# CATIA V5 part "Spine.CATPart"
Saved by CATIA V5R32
Part number: Part1
Bounding box of the stored display mesh (mm): x 97.05 to 179.832, y -8.213 to 8.213, z -51.727 to 9.115
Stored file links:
  D:\PROJECTS\Project 2022\CATIA V5 6R 2022\Resources\Part Files\c17_catia_v6_6r2022_prt\Spine.CATPart
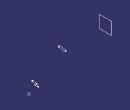
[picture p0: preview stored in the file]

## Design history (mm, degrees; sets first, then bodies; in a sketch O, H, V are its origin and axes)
Body1 (main body)
  Plane1: type Offset, RefPlane yz-plane, Offset 100
  Sketch1 on Plane1, origin (100, 0, 0), H (0, 1, 0), V (0, 0, 1)
    line L1 (-11.8744, 0) -> (18.2844, 0)
    point P1 (-11.8744, 0)
    coincidence: P1 H
    horizontal: L1 H
  Plane2: type Angle, RefPlane Plane1, Direction Sketch1, Angle 30
  Plane3: type Offset, RefPlane Plane2, Offset 75
  Plane4: type Offset, RefPlane Plane3, Offset 20
  Sketch2 on Plane4, origin (157.2724, 0, -90.8013), H (0, 1, 0), V (0.5, 0, 0.866)
    point P1 (0, 45.1194)
    coincidence: P1 V
  Sketch3 on Plane3, origin (139.9519, 0, -80.8013), H (0, 1, 0), V (0.5, 0, 0.866)
    arc A1 centre (0, 54.9362) radius 5.3671 from (5.2994, 54.0869) to (-5.2994, 54.0869) ccw
    point P1 (0, 54.9362)
    arc A2 centre (0, 42.755) radius 3.4394 from (-3.3961, 42.2107) to (3.3961, 42.2107) ccw
    point P2 (0, 42.755)
    line L1 (-5.2994, 54.0869) -> (-3.3961, 42.2107)
    line L2 (5.2994, 54.0869) -> (3.3961, 42.2107)
    coincidence: P1 V, P2 V
    tangency: L1 A1, L1 A2, L2 A1, L2 A2
  Sketch4 on Plane2, origin (75, 0, -43.3013), H (0, 1, 0), V (0.5, 0, 0.866)
    circle A1 centre (0, 52.3122) radius 8.2128
    point P1 (0, 52.3122)
    coincidence: P1 V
